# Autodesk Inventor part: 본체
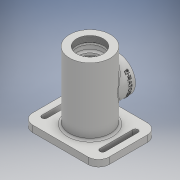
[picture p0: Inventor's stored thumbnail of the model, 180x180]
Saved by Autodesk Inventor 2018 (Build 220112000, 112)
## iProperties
Created: 2021-07
Part Number: 본체
Material: Generic
Document SubType Name: Modeling
Designer: 1class9
Density: 1 g/cm^3
Appearance: Default
Author: 1class9
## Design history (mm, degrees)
sketch "스케치1"
  geometry: C1 r 31 at (0, 0); 1 further point
  constraints: 1 centre point, 1 coincident
  dimensions: "d0" = 62 diameter of C1
extrude "돌출1" new body sketch "스케치1" stored distance "d1" = 102; taper "d2" = 0 deg
sketch "스케치3"
  geometry: L1 (31, -51)-(-31, -51) reference; L2 (-31, -51)-(-31, 51) reference; L3 (-31, 51)-(31, 51) reference; L4 (31, 51)-(31, -51) reference; L5 (42, -5)-(0, -5); L6 (0, -5)-(0, -32); L7 (0, -32)-(42, -32); L8 (42, -32)-(42, -5); 2 further points
  constraints: 8 end point, 2 parallel, 1 horizontal, 1 midpoint, 1 perpendicular, 1 vertical alignment
  dimensions: "d4" = 46 distance between parallel lines of L5 L1; "d5" = 54 diameter of L7 L5; "d6" = 42 distance between parallel lines of L6 L8
revolve "회전1" sketch "스케치3" stored, may be unused: angle "d7" = 90 deg
sketch "스케치4"
  geometry: L1 (-58, -45)-(58, -45); L2 (58, -45)-(58, 45); L3 (58, 45)-(-58, 45); L4 (-58, 45)-(-58, -45); L5 (-58, -45)-(58, 45); L6 (58, -45)-(-58, 45); 1 further point
  constraints: 12 end point, 2 midpoint, 2 parallel, 1 horizontal, 1 perpendicular
  dimensions: "d8" = 116 distance of L2.end L3.end; "d9" = 90 distance of L1.end L2.end
extrude "돌출2" join sketch "스케치4" distance "d10" = 10; taper "d11" = 0 deg
sketch "스케치5"
  geometry: C1 r 35 at (0, 0); 1 further point
  constraints: 1 centre point, 1 coincident
  dimensions: "d12" = 70 diameter of C1
extrude "돌출3" join sketch "스케치5" distance "d13" = 3; taper "d14" = 0 deg
hole "구멍1" diameter "d17" = 40.376; stored, may be unused: countersink angle "d21" = 90 deg, drill point angle "d23" = 118 deg; dims "d15" = 10, "d16" = 10, "d18" = 84, "d19" = 4, "d20" = 2, "d22" = 9
sketch "스케치8"
  geometry: L1 (20.188, 42)-(-20.188, 42) reference; L2 (20.188, 42)-(-20.188, 42) reference; L3 (0, 42)-(24, 42); L4 (24, 42)-(24, 39); L5 (24, 39)-(0, 39); L6 (0, 39)-(0, 42); L7 (0, 39)-(20, 39); L8 (20, 39)-(20, 33); L9 (0, 30)-(0, 39); L10 (0, 30)-(17, 30); L11 (-35, -64)-(35, -64) reference; A1 r 3 centre (17, 33) between (17, 30) and (20, 33); 2 further points
  constraints: 16 end point, 3 horizontal, 3 parallel, 2 perpendicular, 2 point on circle, 2 point on line, 2 tangent, 1 centre point, 1 midpoint
  dimensions: "d24" = 48 diameter of L4 L6; "d25" = 3 distance of L3.end L4.end; "d26" = 9 distance of point (20, 30) L7.end; "d27" = 40 diameter of L8 L9; "d56" = 3 radius of A1 (derived)
revolve "회전2" sketch "스케치8" stored, may be unused: angle "d33" = 90 deg
sketch "스케치9"
  geometry: L1 (42, 22)-(42, -32) reference; L2 (42, -5)-(109.389, -5); L3 (0, 25)-(17.5, 25); L4 (17.5, 25)-(17.5, -35); L5 (17.5, -35)-(0, -35); L6 (0, -8.476)-(17.5, -35); L7 (17.5, 25)-(0, -8.476); L8 (0, 25)-(0, -35); 3 further points
  constraints: 14 end point, 3 point on line, 2 horizontal, 2 midpoint, 2 vertical alignment, 1 horizontal alignment, 1 parallel, 1 perpendicular
  dimensions: "d34" = 60 distance of L3.end L4.end; "d35" = 35 diameter of L4 L8
revolve "회전3" sketch "스케치9" stored, may be unused: angle "d36" = 90 deg
sketch "스케치10"
  geometry: L1 (31, 22)-(42, 22) reference; L2 (42, 22)-(42, -32) reference; L3 (42, -32)-(31, -32) reference; L4 (31, -32)-(31, -51) reference; L5 (31, -51)-(45, -51) reference; L6 (45, -51)-(45, -61) reference; L7 (45, -61)-(35, -61) reference; L8 (35, -61)-(35, -64) reference; L9 (35, -64)-(-35, -64) reference; L10 (-35, -64)-(-35, -61) reference; L11 (-35, -61)-(-45, -61) reference; L12 (-45, -61)-(-45, -51) reference; L13 (-45, -51)-(-31, -51) reference; L14 (-31, -51)-(-31, 51) reference; L15 (-31, 51)-(-20.188, 51) reference; L16 (-20.188, 51)-(-20.188, 42) reference; L17 (-20.188, 42)-(-24, 42) reference; L18 (-24, 42)-(-24, 39) reference; L19 (-24, 39)-(-20, 39) reference; L20 (-20, 39)-(-20, 33) reference; L21 (-17, 30)-(-0.217, 30) reference; L22 (-0.217, 30)-(0, 29.87) reference; L23 (0, 29.87)-(0.217, 30) reference; L24 (0.217, 30)-(17, 30) reference; L25 (20, 33)-(20, 39) reference; L26 (20, 39)-(24, 39) reference; L27 (24, 39)-(24, 42) reference; L28 (24, 42)-(20.188, 42) reference; L29 (20.188, 42)-(20.188, 51) reference; L30 (20.188, 51)-(31, 51) reference; L31 (31, 51)-(31, 22) reference; L32 (-17.5, -35)-(17.5, -35) reference; L33 (17.5, -35)-(17.5, 25) reference; L34 (17.5, 25)-(-17.5, 25) reference; L35 (-17.5, 25)-(-17.5, -35) reference; L36 (17.5, 25)-(-17.5, 25) reference; L37 (0, 25)-(18.5, 25); L38 (18.5, 25)-(18.5, 26.75); L39 (18.5, 26.75)-(0, 26.75); L40 (0, 26.75)-(0, 25); A1 r 3 centre (-17, 33) between (-20, 33) and (-17, 30) reference; A2 r 3 centre (17, 33) between (17, 30) and (20, 33) reference; 1 further point
  constraints: 8 end point, 2 parallel, 1 horizontal, 1 midpoint, 1 perpendicular
  dimensions: "d37" = 1.75 distance of L37.end L38.end; "d38" = 37 diameter of L38 L40
revolve "회전4" sketch "스케치10" stored, may be unused: angle "d39" = 90 deg
sketch "스케치11"
  geometry: L1 (20, 39)-(-20, 39) reference; L2 (17.5, 25)-(-17.5, 25) reference; L3 (17.5, -35)-(-17.5, -35) reference; L4 (18.5, 26.75)-(-18.5, 26.75) reference; L5 (0, 29.87)-(-0.217, 30) reference; L6 (-0.108, 29.935)-(17.392, 29.935); L7 (17.392, 29.935)-(17.392, 26.75); L8 (17.392, 26.75)-(-0.108, 26.75); L9 (-0.108, 26.75)-(-0.108, 29.935); 3 further points
  constraints: 8 end point, 2 parallel, 1 horizontal, 1 midpoint, 1 perpendicular, 1 point on line
  dimensions: "d40" = 35 diameter of L7 L9
revolve "회전5" sketch "스케치11" stored, may be unused: angle "d41" = 90 deg
sketch "스케치12"
  geometry: L1 (-17.5, -35)-(17.5, -35) reference; L2 (17.5, -35)-(17.5, 25) reference; L3 (17.5, 25)-(18.5, 25) reference; L4 (18.5, 25)-(18.5, 26.75) reference; L5 (18.5, 26.75)-(17.392, 26.75) reference; L6 (17.392, 26.75)-(17.392, 29.935) reference; L7 (17.392, 29.935)-(0.108, 29.935) reference; L8 (0.108, 29.935)-(0.217, 30) reference; L9 (0.217, 30)-(17, 30) reference; L10 (20, 33)-(20, 39) reference; L11 (20, 39)-(24, 39) reference; L12 (24, 39)-(24, 42) reference; L13 (24, 42)-(20.188, 42) reference; L14 (20.188, 42)-(20.188, 51) reference; L15 (20.188, 51)-(31, 51) reference; L16 (31, 51)-(31, 22) reference; L17 (31, 22)-(42, 22) reference; L18 (42, 22)-(42, -32) reference; L19 (42, -32)-(31, -32) reference; L20 (31, -32)-(31, -51) reference; L21 (31, -51)-(45, -51) reference; L22 (45, -51)-(45, -61) reference; L23 (45, -61)-(35, -61) reference; L24 (35, -61)-(35, -64) reference; L25 (35, -64)-(-35, -64) reference; L26 (-35, -64)-(-35, -61) reference; L27 (-35, -61)-(-45, -61) reference; L28 (-45, -61)-(-45, -51) reference; L29 (-45, -51)-(-31, -51) reference; L30 (-31, -51)-(-31, 51) reference; L31 (-31, 51)-(-20.188, 51) reference; L32 (-20.188, 51)-(-20.188, 42) reference; L33 (-20.188, 42)-(-24, 42) reference; L34 (-24, 42)-(-24, 39) reference; L35 (-24, 39)-(-20, 39) reference; L36 (-20, 39)-(-20, 33) reference; L37 (-17, 30)-(-0.217, 30) reference; L38 (-0.217, 30)-(-0.108, 29.935) reference; L39 (-0.108, 29.935)-(-17.608, 29.935) reference; L40 (-17.608, 29.935)-(-17.608, 26.75) reference; L41 (-17.608, 26.75)-(-18.5, 26.75) reference; L42 (-18.5, 26.75)-(-18.5, 25) reference; L43 (-18.5, 25)-(-17.5, 25) reference; L44 (-17.5, 25)-(-17.5, -35) reference; L45 (0, -35)-(16, -35); L46 (16, -35)-(16, -37); L47 (13, -40)-(0, -40); L48 (0, -40)-(0, -35); L49 (0, -40)-(10, -40); L50 (10, -40)-(10, -42); L51 (10, -42)-(0, -42); L52 (0, -42)-(0, -40); L53 (0, -42)-(12.2, -42); L54 (12.5, -42.3)-(12.5, -48.6); L55 (12.5, -48.6)-(0, -48.6); L56 (0, -48.6)-(0, -42); A1 r 3 centre (17, 33) between (17, 30) and (20, 33) reference; A2 r 3 centre (-17, 33) between (-20, 33) and (-17, 30) reference; A3 r 3 centre (13, -37) between (13, -40) and (16, -37); A4 r 0.3 centre (12.2, -42.3) between (12.5, -42.3) and (12.2, -42); 3 further points
  constraints: 24 end point, 6 parallel, 4 point on circle, 4 point on line, 4 tangent, 3 horizontal, 3 perpendicular, 2 centre point, 1 midpoint
  dimensions: "d42" = 32 diameter of L46 L48; "d43" = 5 distance of L45.end point (16, -40); "d44" = 20 diameter of L50 L52; "d45" = 2 distance of L49.end L50.end; "d46" = 6.6 distance of point (12.5, -42) L54.end; "d47" = 25 diameter of L54 L56; "d67" = 3 radius of A3; "d68" = 0.3 radius of A4 (derived)
revolve "회전6" sketch "스케치12" stored, may be unused: angle "d48" = 90 deg
sketch "스케치14"
  geometry: L1 (-18.5, 26.75)-(-18.5, 25) reference; L2 (-18.5, 25)-(-17.5, 25) reference; L3 (-17.5, 25)-(-17.5, -35) reference; L4 (-17.5, -35)-(-16, -35) reference; L5 (-16, -35)-(-16, -37) reference; L6 (-13, -40)-(-10, -40) reference; L7 (-10, -40)-(-10, -42) reference; L8 (-10, -42)-(-12.2, -42) reference; L9 (-12.5, -42.3)-(-12.5, -48.6) reference; L10 (-12.5, -48.6)-(12.5, -48.6) reference; L11 (12.5, -48.6)-(12.5, -42.3) reference; L12 (12.2, -42)-(10, -42) reference; L13 (10, -42)-(10, -40) reference; L14 (10, -40)-(13, -40) reference; L15 (16, -37)-(16, -35) reference; L16 (16, -35)-(17.5, -35) reference; L17 (17.5, -35)-(17.5, 25) reference; L18 (17.5, 25)-(18.5, 25) reference; L19 (18.5, 25)-(18.5, 26.75) reference; L20 (18.5, 26.75)-(17.392, 26.75) reference; L21 (17.392, 26.75)-(17.392, 29.935) reference; L22 (17.392, 29.935)-(0.108, 29.935) reference; L23 (0.108, 29.935)-(0.217, 30) reference; L24 (0.217, 30)-(17, 30) reference; L25 (20, 33)-(20, 39) reference; L26 (20, 39)-(24, 39) reference; L27 (24, 39)-(24, 42) reference; L28 (24, 42)-(20.188, 42) reference; L29 (20.188, 42)-(20.188, 51) reference; L30 (20.188, 51)-(31, 51) reference; L31 (31, 51)-(31, 22) reference; L32 (31, 22)-(42, 22) reference; L33 (42, 22)-(42, -32) reference; L34 (42, -32)-(31, -32) reference; L35 (31, -32)-(31, -51) reference; L36 (31, -51)-(45, -51) reference; L37 (45, -51)-(45, -61) reference; L38 (45, -61)-(35, -61) reference; L39 (35, -61)-(35, -64) reference; L40 (35, -64)-(-35, -64) reference; L41 (-35, -64)-(-35, -61) reference; L42 (-35, -61)-(-45, -61) reference; L43 (-45, -61)-(-45, -51) reference; L44 (-45, -51)-(-31, -51) reference; L45 (-31, -51)-(-31, 51) reference; L46 (-31, 51)-(-20.188, 51) reference; L47 (-20.188, 51)-(-20.188, 42) reference; L48 (-20.188, 42)-(-24, 42) reference; L49 (-24, 42)-(-24, 39) reference; L50 (-24, 39)-(-20, 39) reference; L51 (-20, 39)-(-20, 33) reference; L52 (-17, 30)-(-0.217, 30) reference; L53 (-0.217, 30)-(-0.108, 29.935) reference; L54 (-0.108, 29.935)-(-17.608, 29.935) reference; L55 (-17.608, 29.935)-(-17.608, 26.75) reference; L56 (-17.608, 26.75)-(-18.5, 26.75) reference; L57 (12.5, -48.6)-(12.904, -49.3); L58 (12.904, -49.3)-(0, -49.3); L59 (-12.5, -48.6)-(12.5, -48.6) reference; L60 (0, -48.6)-(0, -49.3); L61 (12.5, -48.6)-(0, -48.6); A1 r 3 centre (17, 33) between (17, 30) and (20, 33) reference; A2 r 3 centre (-17, 33) between (-20, 33) and (-17, 30) reference; A3 r 3 centre (-13, -37) between (-16, -37) and (-13, -40) reference; A4 r 0.3 centre (-12.2, -42.3) between (-12.2, -42) and (-12.5, -42.3) reference; A5 r 0.3 centre (12.2, -42.3) between (12.5, -42.3) and (12.2, -42) reference; A6 r 3 centre (13, -37) between (13, -40) and (16, -37) reference; 1 further point
  constraints: 8 end point, 2 horizontal, 1 midpoint, 1 vertical
  dimensions: "d49" = 30 deg angle of L11 L57; "d50" = 0.7 distance between parallel lines of L61 L58
revolve "회전7" sketch "스케치14" stored, may be unused: angle "d51" = 90 deg
sketch "스케치15"
  geometry: L1 (-18.5, 26.75)-(-18.5, 25) reference; L2 (-18.5, 25)-(-17.5, 25) reference; L3 (-17.5, 25)-(-17.5, -35) reference; L4 (-17.5, -35)-(-16, -35) reference; L5 (-16, -35)-(-16, -37) reference; L6 (-13, -40)-(-10, -40) reference; L7 (-10, -40)-(-10, -42) reference; L8 (-10, -42)-(-12.2, -42) reference; L9 (-12.5, -42.3)-(-12.5, -48.6) reference; L10 (-12.5, -48.6)-(-12.904, -49.3) reference; L11 (-12.904, -49.3)-(12.904, -49.3) reference; L12 (12.904, -49.3)-(12.5, -48.6) reference; L13 (12.5, -48.6)-(12.5, -42.3) reference; L14 (12.2, -42)-(10, -42) reference; L15 (10, -42)-(10, -40) reference; L16 (10, -40)-(13, -40) reference; L17 (16, -37)-(16, -35) reference; L18 (16, -35)-(17.5, -35) reference; L19 (17.5, -35)-(17.5, 25) reference; L20 (17.5, 25)-(18.5, 25) reference; L21 (18.5, 25)-(18.5, 26.75) reference; L22 (18.5, 26.75)-(17.392, 26.75) reference; L23 (17.392, 26.75)-(17.392, 29.935) reference; L24 (17.392, 29.935)-(0.108, 29.935) reference; L25 (0.108, 29.935)-(0.217, 30) reference; L26 (0.217, 30)-(17, 30) reference; L27 (20, 33)-(20, 39) reference; L28 (20, 39)-(24, 39) reference; L29 (24, 39)-(24, 42) reference; L30 (24, 42)-(20.188, 42) reference; L31 (20.188, 42)-(20.188, 51) reference; L32 (20.188, 51)-(31, 51) reference; L33 (31, 51)-(31, 22) reference; L34 (31, 22)-(42, 22) reference; L35 (42, 22)-(42, -32) reference; L36 (42, -32)-(31, -32) reference; L37 (31, -32)-(31, -51) reference; L38 (31, -51)-(45, -51) reference; L39 (45, -51)-(45, -61) reference; L40 (45, -61)-(35, -61) reference; L41 (35, -61)-(35, -64) reference; L42 (35, -64)-(-35, -64) reference; L43 (-35, -64)-(-35, -61) reference; L44 (-35, -61)-(-45, -61) reference; L45 (-45, -61)-(-45, -51) reference; L46 (-45, -51)-(-31, -51) reference; L47 (-31, -51)-(-31, 51) reference; L48 (-31, 51)-(-20.188, 51) reference; L49 (-20.188, 51)-(-20.188, 42) reference; L50 (-20.188, 42)-(-24, 42) reference; L51 (-24, 42)-(-24, 39) reference; L52 (-24, 39)-(-20, 39) reference; L53 (-20, 39)-(-20, 33) reference; L54 (-17, 30)-(-0.217, 30) reference; L55 (-0.217, 30)-(-0.108, 29.935) reference; L56 (-0.108, 29.935)-(-17.608, 29.935) reference; L57 (-17.608, 29.935)-(-17.608, 26.75) reference; L58 (-17.608, 26.75)-(-18.5, 26.75) reference; L59 (12.904, -49.3)-(-12.904, -49.3) reference; L60 (0, -49.3)-(13.984, -49.3); L61 (16.762, -51.166)-(22, -64); L62 (-35, -64)-(35, -64) reference; L63 (0, -49.3)-(0, -64); L64 (22, -64)-(0, -64); A1 r 3 centre (13.984, -52.3) between (16.762, -51.166) and (13.984, -49.3); A2 r 3 centre (17, 33) between (17, 30) and (20, 33) reference; A3 r 3 centre (-17, 33) between (-20, 33) and (-17, 30) reference; A4 r 3 centre (-13, -37) between (-16, -37) and (-13, -40) reference; A5 r 0.3 centre (-12.2, -42.3) between (-12.2, -42) and (-12.5, -42.3) reference; A6 r 0.3 centre (12.2, -42.3) between (12.5, -42.3) and (12.2, -42) reference; A7 r 3 centre (13, -37) between (13, -40) and (16, -37) reference; 2 further points
  constraints: 8 end point, 4 point on line, 2 midpoint, 2 point on circle, 2 tangent, 1 centre point, 1 collinear
  dimensions: "d52" = 32 diameter of point (16, -49.3) L63; "d53" = 44 diameter of L61.end L63; "d54" = 3 radius of A1
revolve "회전8" sketch "스케치15" stored, may be unused: angle "d55" = 90 deg
sketch "스케치16"
  geometry: L1 (17.392, 29.935)-(17.392, 26.75) reference; L2 (-0.108, 31.531)-(17.392, 31.531); L3 (17.392, 31.531)-(17.392, 29.003); L4 (17.392, 29.003)-(-0.108, 29.003); L5 (-0.108, 29.003)-(-0.108, 31.531); L6 (18.5, 25)-(18.5, 26.75) reference; L7 (18.5, 26.75)-(17.392, 26.75) reference; L8 (17.392, 26.75)-(17.392, 29.935) reference; L9 (17.392, 29.935)-(0.108, 29.935) reference; L10 (0.108, 29.935)-(0.217, 30) reference; L11 (0.217, 30)-(17, 30) reference; L12 (20, 33)-(20, 39) reference; L13 (20, 39)-(24, 39) reference; L14 (24, 39)-(24, 42) reference; L15 (24, 42)-(20.188, 42) reference; L16 (20.188, 42)-(20.188, 51) reference; L17 (20.188, 51)-(31, 51) reference; L18 (31, 51)-(31, 22) reference; L19 (31, 22)-(42, 22) reference; L20 (42, 22)-(42, -32) reference; L21 (42, -32)-(31, -32) reference; L22 (31, -32)-(31, -51) reference; L23 (31, -51)-(45, -51) reference; L24 (45, -51)-(45, -61) reference; L25 (45, -61)-(35, -61) reference; L26 (35, -61)-(35, -64) reference; L27 (35, -64)-(22, -64) reference; L28 (22, -64)-(16.762, -51.166) reference; L29 (13.984, -49.3)-(12.904, -49.3) reference; L30 (12.904, -49.3)-(12.5, -48.6) reference; L31 (12.5, -48.6)-(12.5, -42.3) reference; L32 (12.2, -42)-(10, -42) reference; L33 (10, -42)-(10, -40) reference; L34 (10, -40)-(13, -40) reference; L35 (16, -37)-(16, -35) reference; L36 (16, -35)-(17.5, -35) reference; L37 (17.5, -35)-(17.5, 25) reference; L38 (17.5, 25)-(18.5, 25) reference; L39 (-18.5, 26.75)-(-18.5, 25) reference; L40 (-18.5, 25)-(-17.5, 25) reference; L41 (-17.5, 25)-(-17.5, -35) reference; L42 (-17.5, -35)-(-16, -35) reference; L43 (-16, -35)-(-16, -37) reference; L44 (-13, -40)-(-10, -40) reference; L45 (-10, -40)-(-10, -42) reference; L46 (-10, -42)-(-12.2, -42) reference; L47 (-12.5, -42.3)-(-12.5, -48.6) reference; L48 (-12.5, -48.6)-(-12.904, -49.3) reference; L49 (-12.904, -49.3)-(-13.984, -49.3) reference; L50 (-16.762, -51.166)-(-22, -64) reference; L51 (-22, -64)-(-35, -64) reference; L52 (-35, -64)-(-35, -61) reference; L53 (-35, -61)-(-45, -61) reference; L54 (-45, -61)-(-45, -51) reference; L55 (-45, -51)-(-31, -51) reference; L56 (-31, -51)-(-31, 51) reference; L57 (-31, 51)-(-20.188, 51) reference; L58 (-20.188, 51)-(-20.188, 42) reference; L59 (-20.188, 42)-(-24, 42) reference; L60 (-24, 42)-(-24, 39) reference; L61 (-24, 39)-(-20, 39) reference; L62 (-20, 39)-(-20, 33) reference; L63 (-17, 30)-(-0.217, 30) reference; L64 (-0.217, 30)-(-0.108, 29.935) reference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; A1 r 3 centre (17, 33) between (17, 30) and (20, 33) reference; A2 r 3 centre (13.984, -52.3) between (16.762, -51.166) and (13.984, -49.3) reference; A3 r 3 centre (-13.984, -52.3) between (-13.984, -49.3) and (-16.762, -51.166) reference; A4 r 3 centre (-17, 33) between (-20, 33) and (-17, 30) reference; A5 r 0.3 centre (12.2, -42.3) between (12.5, -42.3) and (12.2, -42) reference; A6 r 3 centre (13, -37) between (13, -40) and (16, -37) reference; A7 r 3 centre (-13, -37) between (-16, -37) and (-13, -40) reference; A8 r 0.3 centre (-12.2, -42.3) between (-12.2, -42) and (-12.5, -42.3) reference; 2 further points
  constraints: 8 end point, 2 parallel, 1 horizontal, 1 midpoint, 1 perpendicular, 1 point on line, 1 vertical alignment
  dimensions: "d57" = 2.52886 distance of L2.end L3.end; "d58" = 19.46862 distance between parallel lines of L17 L2
revolve "회전9" sketch "스케치16" stored, may be unused: angle "d59" = 90 deg
sketch "스케치17"
  geometry: L1 (18.5, 25)-(18.5, 26.75) reference; L2 (18.5, 26.75)-(17.392, 26.75) reference; L3 (17.392, 26.75)-(17.392, 30.026) reference; L4 (20, 33)-(20, 39) reference; L5 (20, 39)-(24, 39) reference; L6 (24, 39)-(24, 42) reference; L7 (24, 42)-(20.188, 42) reference; L8 (20.188, 42)-(20.188, 51) reference; L9 (20.188, 51)-(31, 51) reference; L10 (31, 51)-(31, 22) reference; L11 (31, 22)-(42, 22) reference; L12 (42, 22)-(42, -32) reference; L13 (42, -32)-(31, -32) reference; L14 (31, -32)-(31, -51) reference; L15 (31, -51)-(45, -51) reference; L16 (45, -51)-(45, -61) reference; L17 (45, -61)-(35, -61) reference; L18 (35, -61)-(35, -64) reference; L19 (35, -64)-(22, -64) reference; L20 (22, -64)-(16.762, -51.166) reference; L21 (13.984, -49.3)-(12.904, -49.3) reference; L22 (12.904, -49.3)-(12.5, -48.6) reference; L23 (12.5, -48.6)-(12.5, -42.3) reference; L24 (12.2, -42)-(10, -42) reference; L25 (10, -42)-(10, -40) reference; L26 (10, -40)-(13, -40) reference; L27 (16, -37)-(16, -35) reference; L28 (16, -35)-(17.5, -35) reference; L29 (17.5, -35)-(17.5, 25) reference; L30 (17.5, 25)-(18.5, 25) reference; L31 (-18.5, 26.75)-(-18.5, 25) reference; L32 (-18.5, 25)-(-17.5, 25) reference; L33 (-17.5, 25)-(-17.5, -35) reference; L34 (-17.5, -35)-(-16, -35) reference; L35 (-16, -35)-(-16, -37) reference; L36 (-13, -40)-(-10, -40) reference; L37 (-10, -40)-(-10, -42) reference; L38 (-10, -42)-(-12.2, -42) reference; L39 (-12.5, -42.3)-(-12.5, -48.6) reference; L40 (-12.5, -48.6)-(-12.904, -49.3) reference; L41 (-12.904, -49.3)-(-13.984, -49.3) reference; L42 (-16.762, -51.166)-(-22, -64) reference; L43 (-22, -64)-(-35, -64) reference; L44 (-35, -64)-(-35, -61) reference; L45 (-35, -61)-(-45, -61) reference; L46 (-45, -61)-(-45, -51) reference; L47 (-45, -51)-(-31, -51) reference; L48 (-31, -51)-(-31, 51) reference; L49 (-31, 51)-(-20.188, 51) reference; L50 (-20.188, 51)-(-20.188, 42) reference; L51 (-20.188, 42)-(-24, 42) reference; L52 (-24, 42)-(-24, 39) reference; L53 (-24, 39)-(-20, 39) reference; L54 (-20, 39)-(-20, 33) reference; L55 (-17.608, 30.062)-(-17.608, 26.75) reference; L56 (-17.608, 26.75)-(-18.5, 26.75) reference; L57 (0, 14)-(23, 14); L58 (26, 11)-(26, -21); L59 (23, -24)-(0, -24); L60 (0, -24)-(0, 14); L61 (42, 22)-(42, -32) reference; L62 (42, -5)-(71.492, -5); A1 r 3 centre (17, 33) between (17.392, 30.026) and (20, 33) reference; A2 r 3 centre (13.984, -52.3) between (16.762, -51.166) and (13.984, -49.3) reference; A3 r 3 centre (-13.984, -52.3) between (-13.984, -49.3) and (-16.762, -51.166) reference; A4 r 3 centre (-17, 33) between (-20, 33) and (-17.608, 30.062) reference; A5 r 3 centre (23, 11) between (26, 11) and (23, 14); A6 r 3 centre (23, -21) between (23, -24) and (26, -21); A7 r 0.3 centre (12.2, -42.3) between (12.5, -42.3) and (12.2, -42) reference; A8 r 3 centre (13, -37) between (13, -40) and (16, -37) reference; A9 r 3 centre (-13, -37) between (-16, -37) and (-13, -40) reference; A10 r 0.3 centre (-12.2, -42.3) between (-12.2, -42) and (-12.5, -42.3) reference; 6 further points
  constraints: 10 end point, 4 midpoint, 4 point on circle, 4 point on line, 4 tangent, 2 centre point, 2 horizontal, 2 parallel, 1 equal radius, 1 horizontal alignment, 1 perpendicular, 1 vertical alignment
  dimensions: "d60" = 38 distance of point (26, 14) point (26, -24); "d61" = 52 diameter of L58 L60; "d62" = 3 radius of A5 (derived)
revolve "회전10" sketch "스케치17" stored, may be unused: angle "d63" = 90 deg
chamfer "모따기1" distance "d64" = 1; stored, may be unused: second distance "d65" = 2, angle "d66" = 45 deg
sketch "스케치18"
  geometry: C1 r 27 at (0, 0) reference; C2 r 16 at (0, 0); 1 further point
  constraints: 1 centre point, 1 coincident
  dimensions: "d70" = 32 diameter of C2
extrude "돌출4" cut sketch "스케치18" distance "d71" = 43.25; taper "d72" = 0 deg
chamfer "모따기2" distance "d73" = 1; stored, may be unused: second distance "d74" = 2, angle "d75" = 45 deg
fillet "모깎기1" dims "d76" = 3
node "작업 평면1"
sketch "스케치19"
  geometry: L1 (21, 27)-(21, -27) reference; 3 further points
  constraints: 1 horizontal alignment, 1 midpoint, 1 other
  dimensions: "d77" = 8 distance from line of L1 point (13, 0)
feature "엠보싱1" sketch "스케치19" dims "d10" = 10, "d11" = 0, "d78" = 0.5, "d79" = 0
sketch "스케치20"
  geometry: L1 (44, 25)-(44, -25); L2 (40, 25)-(40, -25); L3 (48, -25)-(48, 25); L4 (0, 0)-(0, -65.673); L5 (-44, 25)-(-44, -25); L6 (-40, 25)-(-40, -25); L7 (-48, -25)-(-48, 25); A1 r 4 centre (44, 25) between (48, 25) and (40, 25); A2 r 4 centre (44, -25) between (40, -25) and (48, -25); A3 r 4 centre (-44, 25) between (-40, 25) and (-48, 25); A4 r 4 centre (-44, -25) between (-48, -25) and (-40, -25); 2 further points
  constraints: 18 end point, 8 point on circle, 7 symmetric about line, 4 centre point, 4 tangent, 2 vertical, 1 horizontal alignment, 1 midpoint, 1 parallel, 2 other
  dimensions: "d80" = 4 radius of A1; "d81" = 50 distance of L1.start L1.end; "d82" = 44 distance from line of L1 L4.start
extrude "돌출5" cut sketch "스케치20" distance "d83" = 14.25; taper "d84" = 0 deg
sketch "스케치21"
  geometry: L1 (58, 46)-(-58, 46) reference; L2 (-58, 46)-(-58, 56) reference; L3 (-58, 56)-(58, 56) reference; L4 (58, 56)-(58, 46) reference; C1 r 27 at (0, 0) reference; C2 r 17 at (0, 0) reference; A1 r 22 centre (0, 0) between (-22, 0) and (22, 0); 1 further point
  constraints: 2 point on circle, 1 centre point, 1 coincident
  dimensions: "d85" = 44 diameter of A1
hole "구멍2" sketch "스케치21" at (-22, 0), (22, 0) diameter "d86" = 2.459; stored, may be unused: countersink angle "d90" = 90 deg, drill point angle "d92" = 118 deg; dims "d87" = 6, "d88" = 4, "d89" = 2, "d91" = 8
fillet "모깎기2" dims "d93" = 16
fillet "모깎기5" dims "d96" = 0.3
node "솔리드1"
node "투영된 루프1"
node "투영된 루프2"
node "투영된 루프3"
node "투영된 루프4"
node "절단 모서리 투영1"
node "절단 모서리 투영3"
node "절단 모서리 투영4"
node "절단 모서리 투영6"
node "절단 모서리 투영7"
node "절단 모서리 투영8"
node "절단 모서리 투영9"
node "절단 모서리 투영10"
